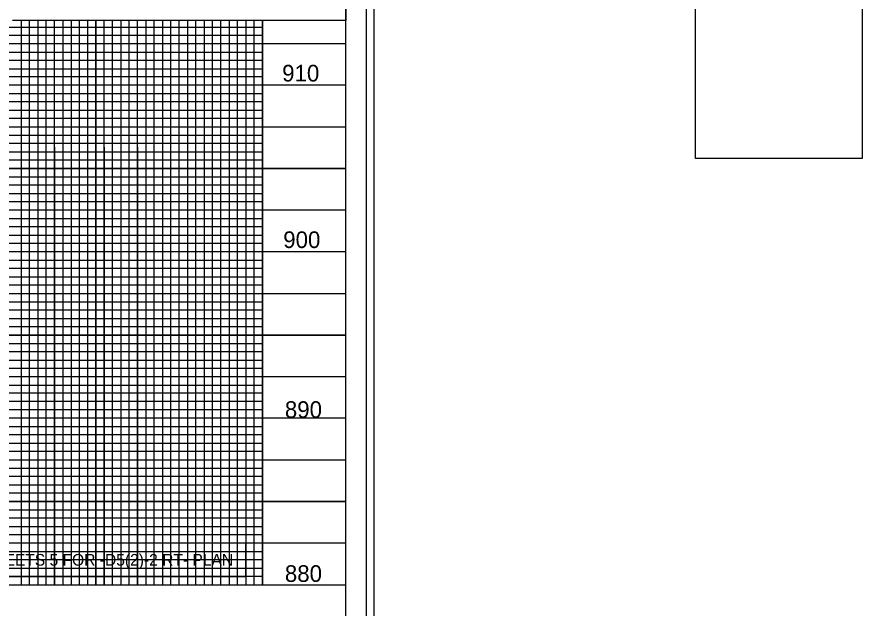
# Model space of a CAD drawing. Extents: x 1648435 to 1651603, y 802691 to 845762.
# Drawn here: x 1650332 to 1650839, y 803252 to 803607 of the extents above; entities that cross this region are included whole.
import ezdxf

# ---------------------------------------------------------------- set-up
doc = ezdxf.new("R2010")
doc.units = 0
for name, color, linetype in [('Exist Vertical Profile Vertical Axis Label', 7, 'Continuous'), ('Prop Dimension', 7, 'Continuous'), ('Prop Grid Mask', 7, 'Continuous'), ('Sheet DOT Grid CELL', 7, 'Continuous'), ('Sheet Layout Profile Border Port 1', 7, 'Continuous'), ('Sheet Plot Border Inside CELL', 7, 'Continuous'), ('Sheet Plot Border Outside CELL', 7, 'Continuous'), ('Sheet Profile CELL', 7, 'Continuous'), ('Sheet Profile Grid Major CELL', 7, 'Continuous'), ('Sheet Profile Grid Middle CELL', 7, 'Continuous'), ('Sheet Profile Grid Minor CELL', 7, 'Continuous'), ('Sheet Sticker Exception Certification CELL', 7, 'Continuous')]:
    doc.layers.add(name, color=color, linetype=linetype)

msp = doc.modelspace()

# ---------------------------------------------------------------- linework, layer by layer
at = {"layer": 'Prop Grid Mask'}
msp.add_lwpolyline([(1650285.28, 803291.02), (1650285.28, 803271.02), (1650469.28, 803271.02), (1650469.28, 803291.02)], close=True, dxfattribs=at)
at = {"layer": 'Sheet DOT Grid CELL'}
for p, q in [((1650379.28, 803266.02), (1650379.28, 803604.97)), ((1650429.28, 803266.02), (1650429.28, 803604.97)), ((1650479.28, 803266.02), (1650479.28, 803604.97)), ((1650529.28, 803566.02), (1649029.28, 803566.02)), ((1650529.28, 803516.02), (1649029.28, 803516.02)), ((1650529.28, 803466.02), (1649029.28, 803466.02)), ((1650529.28, 803416.02), (1649029.28, 803416.02)), ((1650529.28, 803366.02), (1649029.28, 803366.02)), ((1650529.28, 803316.02), (1649029.28, 803316.02))]:
    msp.add_line(p, q, dxfattribs=at)
at = {"layer": 'Sheet Layout Profile Border Port 1'}
msp.add_lwpolyline([(1649079.28, 803604.97), (1649079.28, 803266.02), (1650479.28, 803266.02), (1650479.28, 803604.97)], dxfattribs=at)
at = {"layer": 'Sheet Plot Border Inside CELL'}
msp.add_lwpolyline([(1648875.28, 802713.47), (1650541.78, 802713.47), (1650541.78, 803768.57), (1648875.28, 803768.57)], close=True, dxfattribs=at)
at = {"layer": 'Sheet Plot Border Outside CELL'}
msp.add_lwpolyline([(1648862.28, 802691.02), (1650546.28, 802691.02), (1650546.28, 803791.02), (1648862.28, 803791.02)], close=True, dxfattribs=at)
at = {"layer": 'Sheet Profile CELL'}
msp.add_line((1649029.28, 803266.02), (1650529.28, 803266.02), dxfattribs=at)
for points in [[(1650529.28, 803766.02), (1649029.28, 803766.02), (1649029.28, 802716.02), (1650529.28, 802716.02)], [(1650739.4, 803634.66), (1650839.4, 803634.66), (1650839.4, 803522.16), (1650739.4, 803522.16)]]:
    msp.add_lwpolyline(points, close=True, dxfattribs=at)
at = {"layer": 'Sheet Profile Grid Major CELL'}
for points in [[(1650479.28, 803604.97), (1650479.28, 803266.02), (1650529.28, 803266.02), (1650529.28, 803616.02)], [(1650379.28, 803604.97), (1650379.28, 803266.02), (1650429.28, 803266.02), (1650429.28, 803266.02), (1650429.28, 803604.97)], [(1650529.28, 803566.02), (1649029.28, 803566.02), (1649029.28, 803516.02), (1650529.28, 803516.02)], [(1650529.28, 803466.02), (1649029.28, 803466.02), (1649029.28, 803416.02), (1650529.28, 803416.02)], [(1650529.28, 803366.02), (1649029.28, 803366.02), (1649029.28, 803366.02), (1649029.28, 803316.02), (1650529.28, 803316.02)]]:
    msp.add_lwpolyline(points, dxfattribs=at)
at = {"layer": 'Sheet Profile Grid Middle CELL'}
for points in [[(1650304.28, 803738.96), (1650304.28, 803266.02), (1650354.28, 803266.02), (1650354.28, 803604.97)], [(1650354.28, 803528.82), (1650354.28, 803266.02), (1650404.28, 803266.02), (1650404.28, 803604.97)], [(1650404.28, 803528.82), (1650404.28, 803266.02), (1650454.28, 803266.02), (1650454.28, 803604.97)], [(1650529.28, 803591.02), (1649029.28, 803591.02), (1649029.28, 803541.02), (1650354.28, 803541.02)], [(1650354.28, 803541.02), (1650529.28, 803541.02)], [(1650354.28, 803541.02), (1650529.28, 803541.02)], [(1650529.28, 803491.02), (1649029.28, 803491.02), (1649029.28, 803441.02), (1650529.28, 803441.02)], [(1650529.28, 803391.02), (1649029.28, 803391.02), (1649029.28, 803341.02), (1650529.28, 803341.02)], [(1650529.28, 803291.02), (1649029.28, 803291.02)]]:
    msp.add_lwpolyline(points, dxfattribs=at)
at = {"layer": 'Sheet Profile Grid Minor CELL'}
for p, q in [((1649079.28, 803601.02), (1650479.28, 803601.02)), ((1650479.28, 803581.02), (1649079.28, 803581.02)), ((1649079.28, 803576.02), (1650479.28, 803576.02)), ((1650479.28, 803556.02), (1649079.28, 803556.02)), ((1649079.28, 803551.02), (1650479.28, 803551.02)), ((1650479.28, 803531.02), (1649079.28, 803531.02)), ((1649079.28, 803526.02), (1650479.28, 803526.02)), ((1650479.28, 803521.02), (1649079.28, 803521.02)), ((1649079.28, 803511.02), (1650479.28, 803511.02)), ((1650479.28, 803506.02), (1649079.28, 803506.02)), ((1649079.28, 803501.02), (1650479.28, 803501.02)), ((1650479.28, 803496.02), (1649079.28, 803496.02)), ((1649079.28, 803486.02), (1650479.28, 803486.02)), ((1650479.28, 803481.02), (1649079.28, 803481.02)), ((1649079.28, 803476.02), (1650479.28, 803476.02)), ((1650479.28, 803471.02), (1649079.28, 803471.02)), ((1649079.28, 803461.02), (1650479.28, 803461.02)), ((1650479.28, 803456.02), (1649079.28, 803456.02)), ((1649079.28, 803451.02), (1650479.28, 803451.02)), ((1650479.28, 803446.02), (1649079.28, 803446.02)), ((1649079.28, 803436.02), (1650479.28, 803436.02)), ((1650479.28, 803431.02), (1649079.28, 803431.02)), ((1649079.28, 803426.02), (1650479.28, 803426.02)), ((1650479.28, 803421.02), (1649079.28, 803421.02)), ((1649079.28, 803411.02), (1650479.28, 803411.02)), ((1650479.28, 803406.02), (1649079.28, 803406.02)), ((1649079.28, 803401.02), (1650479.28, 803401.02)), ((1650479.28, 803396.02), (1649079.28, 803396.02)), ((1649079.28, 803386.02), (1650479.28, 803386.02)), ((1650479.28, 803381.02), (1649079.28, 803381.02)), ((1650479.28, 803376.02), (1649079.28, 803376.02)), ((1650479.28, 803371.02), (1649079.28, 803371.02)), ((1649079.28, 803361.02), (1650479.28, 803361.02)), ((1650479.28, 803356.02), (1649079.28, 803356.02)), ((1649079.28, 803351.02), (1650479.28, 803351.02)), ((1650479.28, 803346.02), (1649079.28, 803346.02)), ((1649079.28, 803336.02), (1650479.28, 803336.02)), ((1650479.28, 803331.02), (1649079.28, 803331.02)), ((1649079.28, 803326.02), (1650479.28, 803326.02)), ((1650479.28, 803321.02), (1649079.28, 803321.02)), ((1649079.28, 803311.02), (1650479.28, 803311.02)), ((1650479.28, 803306.02), (1649079.28, 803306.02)), ((1649079.28, 803301.02), (1650479.28, 803301.02)), ((1650479.28, 803296.02), (1649079.28, 803296.02)), ((1649079.28, 803286.02), (1650479.28, 803286.02)), ((1650479.28, 803281.02), (1649079.28, 803281.02)), ((1649079.28, 803276.02), (1650479.28, 803276.02))]:
    msp.add_line(p, q, dxfattribs=at)
for points in [[(1650334.28, 803604.97), (1650334.28, 803266.02), (1650339.28, 803266.02), (1650339.28, 803604.97)], [(1650344.28, 803604.97), (1650344.28, 803266.02), (1650349.28, 803266.02), (1650349.28, 803604.97)], [(1650359.28, 803604.97), (1650359.28, 803266.02), (1650359.28, 803266.02), (1650364.28, 803266.02), (1650369.28, 803266.02), (1650369.28, 803604.97)], [(1650364.28, 803604.97), (1650364.28, 803266.02)], [(1650374.28, 803604.97), (1650374.18, 803266.07), (1650379.18, 803266.07), (1650384.28, 803266.02), (1650384.28, 803604.97)], [(1650384.28, 803528.82), (1650384.28, 803266.02), (1650389.28, 803266.02), (1650389.28, 803604.97)], [(1650394.28, 803604.97), (1650394.28, 803266.02), (1650399.28, 803266.02), (1650399.28, 803604.97)], [(1650409.28, 803604.97), (1650409.28, 803266.02), (1650414.28, 803266.02), (1650414.28, 803604.97)], [(1650419.28, 803604.97), (1650419.28, 803266.02), (1650424.28, 803266.02), (1650424.28, 803604.97)], [(1650434.28, 803604.97), (1650434.28, 803266.02), (1650439.28, 803266.02), (1650439.28, 803604.97)], [(1650444.28, 803604.97), (1650444.28, 803266.02), (1650449.28, 803266.02), (1650449.28, 803604.97)], [(1650459.28, 803604.97), (1650459.28, 803266.02), (1650464.28, 803266.02), (1650464.28, 803604.97)], [(1650469.28, 803604.97), (1650469.28, 803266.02), (1650474.28, 803266.02), (1650474.28, 803604.97)], [(1650479.28, 803596.02), (1649079.28, 803596.02), (1649079.28, 803586.02), (1650479.28, 803586.02)], [(1650479.28, 803571.02), (1649079.28, 803571.02), (1649079.28, 803561.02), (1650479.28, 803561.02)], [(1650479.28, 803546.02), (1649079.28, 803546.02), (1649079.28, 803536.02), (1650479.28, 803536.02)], [(1650479.28, 803271.02), (1649079.28, 803271.02)]]:
    msp.add_lwpolyline(points, dxfattribs=at)
at = {"layer": 'Sheet Sticker Exception Certification CELL'}
for p, q in [((1650529.27, 803628.46), (1650529.27, 803604.96)), ((1650529.27, 803628.46), (1650529.27, 803604.96)), ((1650529.27, 803604.97), (1650329.23, 803604.97)), ((1650529.27, 803604.97), (1650329.23, 803604.97))]:
    msp.add_line(p, q, dxfattribs=at)

# ---------------------------------------------------------------- texts
at = {"layer": 'Exist Vertical Profile Vertical Axis Label'}
for s, p in [('910', (1650491.09, 803568.33)), ('900', (1650491.73, 803468.29)), ('890', (1650492.71, 803366.27)), ('880', (1650492.71, 803267.76))]:
    msp.add_text(s, height=10, dxfattribs=at).set_placement(p)
at = {"layer": 'Prop Dimension'}
msp.add_text('SEE SHEETS 5 FOR -D5(2)-2 RT- PLAN', height=7, dxfattribs=at).set_placement((1650290, 803277.52))

doc.saveas('drawing.dxf')
